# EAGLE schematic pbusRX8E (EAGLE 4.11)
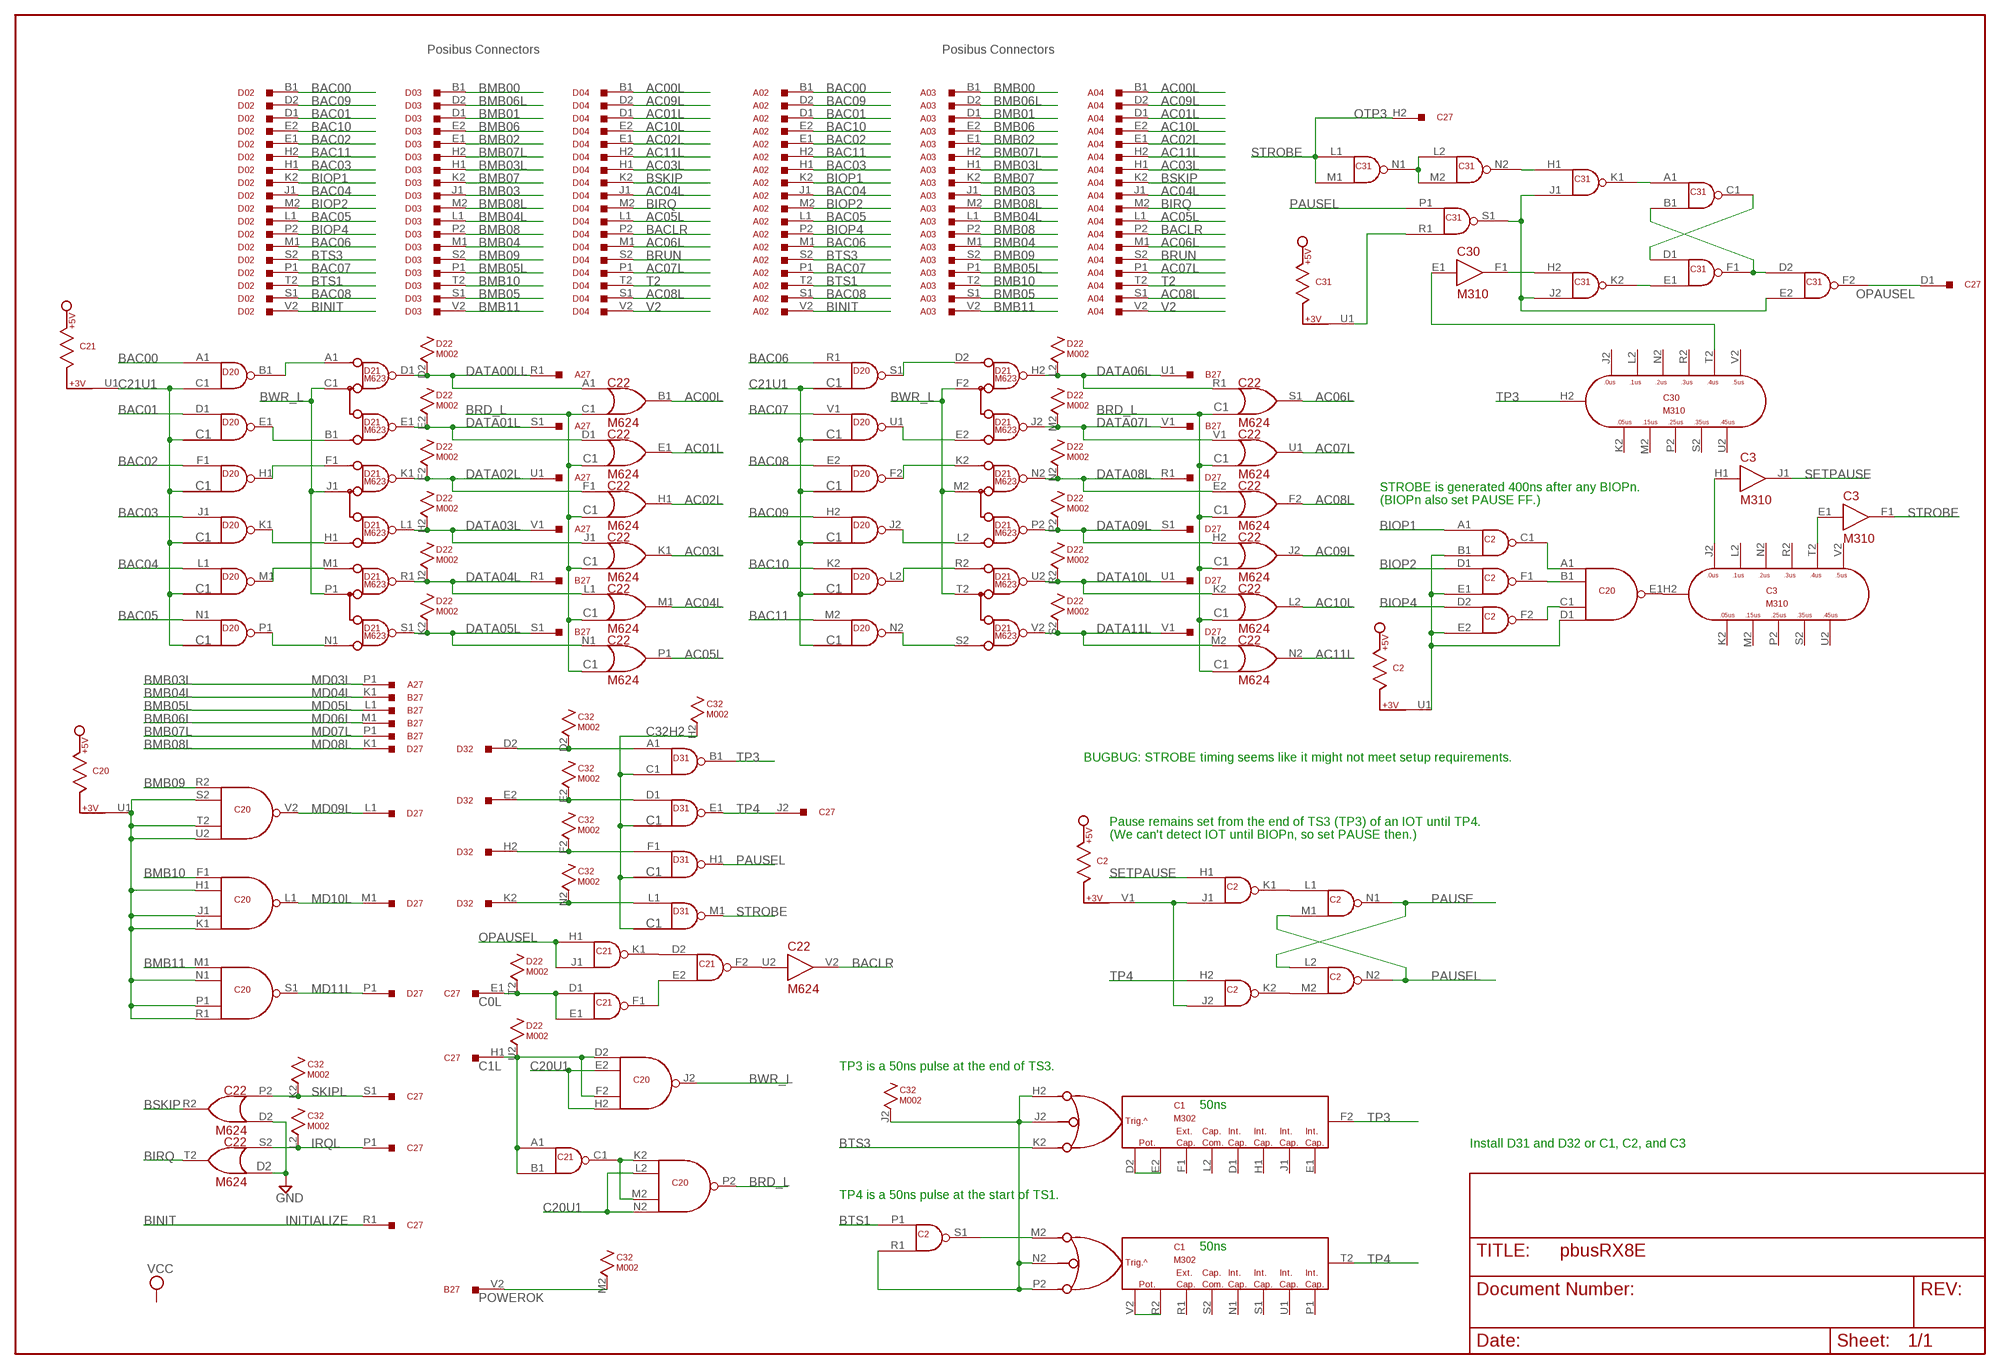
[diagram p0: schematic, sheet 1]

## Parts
A02  M903  [H807]
A03  M903  [H807]
A04  M903  [H807]
A27  M916  [H807]
B27  M916  [H807]
C1  M302  [H807]
C2  M113  [H807]
C3  M310  [H807]
C20  M617  [H807]
C21  M113  [H807]
C22  M624  [H807]
C27  M916  [H807]
C30  M310  [H807]
C31  M113  [H807]
C32  M002  [H807]
D02  M903  [H807]
D03  M903  [H807]
D04  M903  [H807]
D20  M101  [H807]
D21  M623  [H807]
D22  M002  [H807]
D27  M916  [H807]
D31  M101  [H807]
D32  M903  [H807]

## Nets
AC00L: A04.B1 C22.B1(OUT) D04.B1
AC01L: A04.D1 C22.E1(OUT) D04.D1
AC02L: A04.E1 C22.H1(OUT) D04.E1
AC03L: A04.H1 C22.K1(OUT) D04.H1
AC04L: A04.J1 C22.M1(OUT) D04.J1
AC05L: A04.L1 C22.P1(OUT) D04.L1
AC06L: A04.M1 C22.S1(OUT) D04.M1
AC07L: A04.P1 C22.U1(OUT) D04.P1
AC08L: A04.S1 C22.F2(OUT) D04.S1
AC09L: A04.D2 C22.J2(OUT) D04.D2
AC10L: A04.E2 C22.L2(OUT) D04.E2
AC11L: A04.H2 C22.N2(OUT) D04.H2
BAC00: A02.B1 D02.B1 D20.A1(IN1)
BAC01: A02.D1 D02.D1 D20.D1(IN)
BAC02: A02.E1 D02.E1 D20.F1(IN)
BAC03: A02.H1 D02.H1 D20.J1(IN)
BAC04: A02.J1 D02.J1 D20.L1(IN)
BAC05: A02.L1 D02.L1 D20.N1(IN)
BAC06: A02.M1 D02.M1 D20.R1(IN)
BAC07: A02.P1 D02.P1 D20.V1(IN)
BAC08: A02.S1 D02.S1 D20.E2(IN)
BAC09: A02.D2 D02.D2 D20.H2(IN)
BAC10: A02.E2 D02.E2 D20.K2(IN)
BAC11: A02.H2 D02.H2 D20.M2(IN)
BACLR: A04.P2 C22.V2(OUT) D04.P2
BINIT: A02.V2 C27.R1 D02.V2
BIOP1: A02.K2 C2.A1(IN1) D02.K2
BIOP2: A02.M2 C2.D1(IN1) D02.M2
BIOP4: A02.P2 C2.D2(IN1) D02.P2
BIRQ: A04.M2 C22.T2(OUT) D04.M2
BMB00: A03.B1 D03.B1
BMB01: A03.D1 D03.D1
BMB02: A03.E1 D03.E1
BMB03: A03.J1 D03.J1
BMB03L: A03.H1 A27.P1 D03.H1
BMB04: A03.M1 D03.M1
BMB04L: A03.L1 B27.K1 D03.L1
BMB05: A03.S1 D03.S1
BMB05L: A03.P1 B27.L1 D03.P1
BMB06: A03.E2 D03.E2
BMB06L: A03.D2 B27.M1 D03.D2
BMB07: A03.K2 D03.K2
BMB07L: A03.H2 B27.P1 D03.H2
BMB08: A03.P2 D03.P2
BMB08L: A03.M2 D03.M2 D27.K1
BMB09: A03.S2 C20.R2(IN1) D03.S2
BMB10: A03.T2 C20.F1(IN1) D03.T2
BMB11: A03.V2 C20.M1(IN1) D03.V2
BRD_L: C20.P2(OUT) C22.C1(IN2)
BRUN: A04.S2 D04.S2
BSKIP: A04.K2 C22.R2(OUT) D04.K2
BTS1: A02.T2 C2.P1(IN1) D02.T2
BTS3: A02.S2 C1.K2 D02.S2
BWR_L: C20.J2(OUT) D21.C1(C) D21.F2(C) D21.J1(C) D21.M2(C) D21.P1(C) D21.T2(C)
C0L: C21.D1(IN1) C21.E1(IN2) C27.E1 D22.T2
C1L: C20.D2(IN1) C20.F2(IN3) C21.A1(IN1) C21.B1(IN2) C27.H1 D22.U2
C20U1: C20.E2(IN2) C20.H1(IN2) C20.H2(IN4) C20.J1(IN3) C20.K1(IN4) C20.L2(IN2) C20.N1(IN2) C20.N2(IN4) C20.P1(IN3) C20.R1(IN4) C20.S2(IN2) C20.T2(IN3) C20.U1 C20.U2(IN4)
C21U1: C21.U1 D20.C1(IN2)
C32H2: C32.H2 D31.C1(IN2)
DATA00LL: A27.R1 C22.A1(IN1) D21.D1(D) D22.D2
DATA01L: A27.S1 C22.D1(IN) D21.E1(E) D22.E2
DATA02L: A27.U1 C22.F1(IN) D21.K1(D) D22.F2
DATA03L: A27.V1 C22.J1(IN) D21.L1(E) D22.H2
DATA04L: B27.R1 C22.L1(IN) D21.R1(D) D22.J2
DATA05L: B27.S1 C22.N1(IN) D21.S1(E) D22.K2
DATA06L: B27.U1 C22.R1(IN) D21.H2(D) D22.L2
DATA07L: B27.V1 C22.V1(IN) D21.J2(E) D22.M2
DATA08L: C22.E2(IN) D21.N2(D) D22.N2 D27.R1
DATA09L: C22.H2(IN) D21.P2(E) D22.P2 D27.S1
DATA10L: C22.K2(IN) D21.U2(D) D22.R2 D27.U1
DATA11L: C22.M2(IN) D21.V2(E) D22.S2 D27.V1
GND: C22.D2(IN2)
IRQL: C22.S2(IN) C27.P1 C32.L2
MD09L: C20.V2(OUT) D27.L1
MD10L: C20.L1(OUT) D27.M1
MD11L: C20.S1(OUT) D27.P1
N$1: D20.B1(OUT) D21.A1(A)
N$2: D20.E1(OUT) D21.B1(B)
N$3: D20.H1(OUT) D21.F1(A)
N$4: D20.K1(OUT) D21.H1(B)
N$5: D20.P1(OUT) D21.N1(B)
N$6: D20.M1(OUT) D21.M1(A)
N$7: C20.K2(IN1) C20.M2(IN3) C21.C1(OUT)
N$8: D20.N2(OUT) D21.S2(B)
N$9: C32.D2 D31.A1(IN1) D32.D2
N$10: D20.J2(OUT) D21.L2(B)
N$11: D20.U1(OUT) D21.E2(B)
N$12: D20.S1(OUT) D21.D2(A)
N$13: D20.F2(OUT) D21.K2(A)
N$14: D20.L2(OUT) D21.R2(A)
N$15: C32.E2 D31.D1(IN) D32.E2
N$16: C32.F2 D31.F1(IN) D32.H2
N$17: C32.N2 D31.L1(IN) D32.K2
N$18: C31.E2(IN2) C31.J1(IN2) C31.J2(IN2) C31.S1(OUT)
N$19: C21.E2(IN2) C21.F1(OUT)
N$20: C21.D2(IN1) C21.K1(OUT)
N$21: C31.C1(OUT) C31.D1(IN1)
N$22: C31.B1(IN2) C31.D2(IN1) C31.F1(OUT)
N$23: C21.F2(OUT) C22.U2(IN)
N$24: C30.E1(IN) C30.T2
N$25: C30.F1(OUT) C31.H2(IN1)
N$26: C31.L2(IN1) C31.M2(IN2) C31.N1(OUT)
N$27: C3.H2 C20.E1(OUT)
N$28: C31.H1(IN1) C31.N2(OUT)
N$29: C31.A1(IN1) C31.K1(OUT)
N$30: C31.E1(IN2) C31.K2(OUT)
N$31: C3.E1(IN) C3.T2
N$32: C2.F2(OUT) C20.C1(IN3)
N$33: C2.C1(OUT) C20.A1(IN1)
N$34: C2.F1(OUT) C20.B1(IN2)
N$35: C1.D2 C1.E2
N$36: C1.M2(H2) C2.S1(OUT)
N$37: C1.R2(E2) C1.V2(D2)
N$38: C3.H1(IN) C3.J2
N$39: C2.K1(OUT) C2.L1(IN1)
N$40: C1.H2 C1.J2 C1.N2(J2) C1.P2(K2) C2.R1(IN2) C32.J2
N$41: C2.K2(OUT) C2.M2(IN2)
N$42: C31.R1(IN2) C31.U1
N$43: C2.B1(IN2) C2.E1(IN2) C2.E2(IN2) C2.U1 C20.D1(IN4)
N$44: C2.J1(IN2) C2.J2(IN2) C2.V1
OPAUSEL: C21.H1(IN1) C21.J1(IN2) C27.D1 C31.F2(OUT)
PAUSE: C2.L2(IN1) C2.N1(OUT)
PAUSEL: C2.M1(IN2) C2.N2(OUT) C31.P1(IN1) D31.H1(OUT)
POWEROK: B27.V2 C32.M2
SETPAUSE: C2.H1(IN1) C3.J1(OUT)
SKIPL: C22.P2(IN1) C27.S1 C32.K2
STROBE: C3.F1(OUT) C27.H2 C31.L1(IN1) C31.M1(IN2) D31.M1(OUT)
T2: A04.T2 D04.T2
TP3: C1.F2 C30.H2 D31.B1(OUT)
TP4: C1.T2(F2) C2.H2(IN1) C27.J2 D31.E1(OUT)
V2: A04.V2 D04.V2
Unconnected: A27.A1 A27.A2 A27.B1 A27.B2 A27.C1 A27.C2 A27.D1 A27.D2 A27.E1 A27.E2 A27.F1 A27.F2 A27.H1 A27.H2 A27.J1 A27.J2 A27.K1 A27.K2 A27.L1 A27.L2 A27.M1 A27.M2 A27.N1 A27.N2 A27.P2 A27.R2 A27.S2 A27.T1 A27.T2 A27.U2 A27.V2 B27.A1 B27.A2 B27.B1 B27.B2 B27.C1 B27.C2 B27.D1 B27.D2 B27.E1 B27.E2 B27.F1 B27.F2 B27.H1 B27.H2 B27.J1 B27.J2 B27.K2 B27.L2 B27.M2 B27.N1 B27.N2 B27.P2 B27.R2 B27.S2 B27.T1 B27.T2 B27.U2 C1.D1 C1.E1 C1.F1 C1.H1 C1.J1 C1.L2 C1.N1(D1) C1.P1(E1) C1.R1(F1) C1.S1(H1) C1.S2(L2) C1.U1(J1) C2.P2(IN1) C2.R2(IN2) C2.S2(OUT) C2.T2(IN1) C2.U2(IN2) C2.V2(OUT) C3.K2 C3.L2 C3.M2 C3.N2 C3.P2 C3.R2 C3.S2 C3.U2 C3.V2 C20.V1 C21.H2(IN1) C21.J2(IN2) C21.K2(OUT) C21.L1(IN1) C21.L2(IN1) C21.M1(IN2) C21.M2(IN2) C21.N1(OUT) C21.N2(OUT) C21.P1(IN1) C21.P2(IN1) C21.R1(IN2) C21.R2(IN2) C21.S1(OUT) C21.S2(OUT) C21.T2(IN1) C21.U2(IN2) C21.V1 C21.V2(OUT) C27.A1 C27.A2 C27.B1 C27.B2 C27.C1 C27.C2 C27.D2 C27.E2 C27.F1 C27.F2 C27.J1 C27.K1 C27.K2 C27.L1 C27.L2 C27.M1 C27.M2 C27.N1 C27.N2 C27.P2 C27.R2 C27.S2 C27.T1 C27.T2 C27.U1 C27.U2 C27.V1 C27.V2 C30.H1(IN) C30.J1(OUT) C30.J2 C30.K2 C30.L2 C30.M2 C30.N2 C30.P2 C30.R2 C30.S2 C30.U2 C30.V2 C31.P2(IN1) C31.R2(IN2) C31.S2(OUT) C31.T2(IN1) C31.U2(IN2) C31.V1 C31.V2(OUT) C32.P2 C32.R2 C32.S2 C32.T2 C32.U2 C32.V2 D20.P2(IN) D20.R2(OUT) D20.S2(IN) D20.T2(OUT) D20.U2(IN) D20.V2(OUT) D22.V2 D27.A1 D27.A2 D27.B1 D27.B2 D27.C1 D27.C2 D27.D1 D27.D2 D27.E1 D27.E2 D27.F1 D27.F2 D27.H1 D27.H2 D27.J1 D27.J2 D27.K2 D27.L2 D27.M2 D27.N1 D27.N2 D27.P2 D27.R2 D27.S2 D27.T1 D27.T2 D27.U2 D27.V2 D31.E2(IN) D31.F2(OUT) D31.H2(IN) D31.J1(IN) D31.J2(OUT) D31.K1(OUT) D31.K2(IN) D31.L2(OUT) D31.M2(IN) D31.N1(IN) D31.N2(OUT) D31.P1(OUT) D31.P2(IN) D31.R1(IN) D31.R2(OUT) D31.S1(OUT) D31.S2(IN) D31.T2(OUT) D31.U1(OUT) D31.U2(IN) D31.V1(IN) D31.V2(OUT) D32.B1 D32.D1 D32.E1 D32.H1 D32.J1 D32.L1 D32.M1 D32.M2 D32.P1 D32.P2 D32.S1 D32.S2 D32.T2 D32.V2

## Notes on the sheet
- Posibus Connectors | Posibus Connectors
- OTP3
- STROBE is generated 400ns after any BIOPn.
- (BIOPn also set PAUSE FF.)
- MD03L
- MD04L
- MD05L
- MD06L
- MD07L
- MD08L
- BUGBUG: STROBE timing seems like it might not meet setup requirements.
- Pause remains set from the end of TS3 (TP3) of an IOT until TP4.
- (We can't detect IOT until BIOPn, so set PAUSE then.)
- TP3 is a 50ns pulse at the end of TS3.
- 50ns
- Install D31 and D32 or C1, C2, and C3
- TP4 is a 50ns pulse at the start of TS1.
- INITIALIZE
- 50ns

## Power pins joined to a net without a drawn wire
GND: A02.A1 A02.C1 A02.C2 A02.F1 A02.F2 A02.J2 A02.K1 A02.L2 A02.N1 A02.N2 A02.R1 A02.R2 A02.T1 A02.U2 A03.A1 A03.C1 A03.C2 A03.F1 A03.F2 A03.J2 A03.K1 A03.L2 A03.N1 A03.N2 A03.R1 A03.R2 A03.T1 A03.U2 A04.A1 A04.C1 A04.C2 A04.F1 A04.F2 A04.J2 A04.K1 A04.L2 A04.N1 A04.N2 A04.R1 A04.R2 A04.T1 A04.U2 C1.C2(GND) C1.T1(GND) C2.C2(GND) C2.T1(GND) C3.C2(GND) C3.T1(GND) C20.C2(GND) C20.T1(GND) C21.C2(GND) C21.T1(GND) C22.C2(GND) C22.T1(GND) C30.C2(GND) C30.T1(GND) C31.C2(GND) C31.T1(GND) C32.C2(GND) D02.A1 D02.C1 D02.C2 D02.F1 D02.F2 D02.J2 D02.K1 D02.L2 D02.N1 D02.N2 D02.R1 D02.R2 D02.T1 D02.U2 D03.A1 D03.C1 D03.C2 D03.F1 D03.F2 D03.J2 D03.K1 D03.L2 D03.N1 D03.N2 D03.R1 D03.R2 D03.T1 D03.U2 D04.A1 D04.C1 D04.C2 D04.F1 D04.F2 D04.J2 D04.K1 D04.L2 D04.N1 D04.N2 D04.R1 D04.R2 D04.T1 D04.U2 D20.C2(GND) D20.T1(GND) D21.C2(GND) D21.T1(GND) D21.U1(GND) D21.V1(GND) D22.C2(GND) D31.C2(GND) D31.T1(GND) D32.A1 D32.C1 D32.C2 D32.F1 D32.F2 D32.J2 D32.K1 D32.L2 D32.N1 D32.N2 D32.R1 D32.R2 D32.T1 D32.U2
VCC: C1.A2(VCC) C2.A2(VCC) C3.A2(VCC) C20.A2(VCC) C21.A2(VCC) C22.A2(VCC) C30.A2(VCC) C31.A2(VCC) C32.A2(VCC) D20.A2(VCC) D21.A2(VCC) D22.A2(VCC) D31.A2(VCC)

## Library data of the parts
A02-A04 D02-D04 D32 = dec-m:M903: Two-sided Posibus cable/connector.
A27 B27 C27 D27 = dec-m:M916: Simple 36 pin connector/wire cable
C1 = dec-m:M302: Dual one-shot
C2 C21 C31 = dec-m:M113: 10 2-input NAND Gates
C3 C30 = dec-m:M310: Tapped Delay Line
C20 = dec-m:M617: 6 4-input NAND Buffers
C22 = dec-m:M624: Bus Data Interface The M101 contains 15 two-input NAND gates. One input of each gate is tied to a common line so that all data signals can be enabled simultaneously. Each data signal presents one TTL load. The common input presents 15 loads. Each output can drive 10 loads. Power: 5V@82ma (max.)
C32 D22 = dec-m:M002: 15 Clamped Loads
D20 D31 = dec-m:M101: Bus Data Interface The M101 contains 15 two-input NAND gates. One input of each gate is tied to a common line so that all data signals can be enabled simultaneously. Each data signal presents one TTL load. The common input presents 15 loads. Each output can drive 10 loads. Power: 5V@82ma (max.)
D21 = dec-m:M623: 6 Dual Bus Drivers

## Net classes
1 Supply: width 1.905 mm, drill 0.508 mm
